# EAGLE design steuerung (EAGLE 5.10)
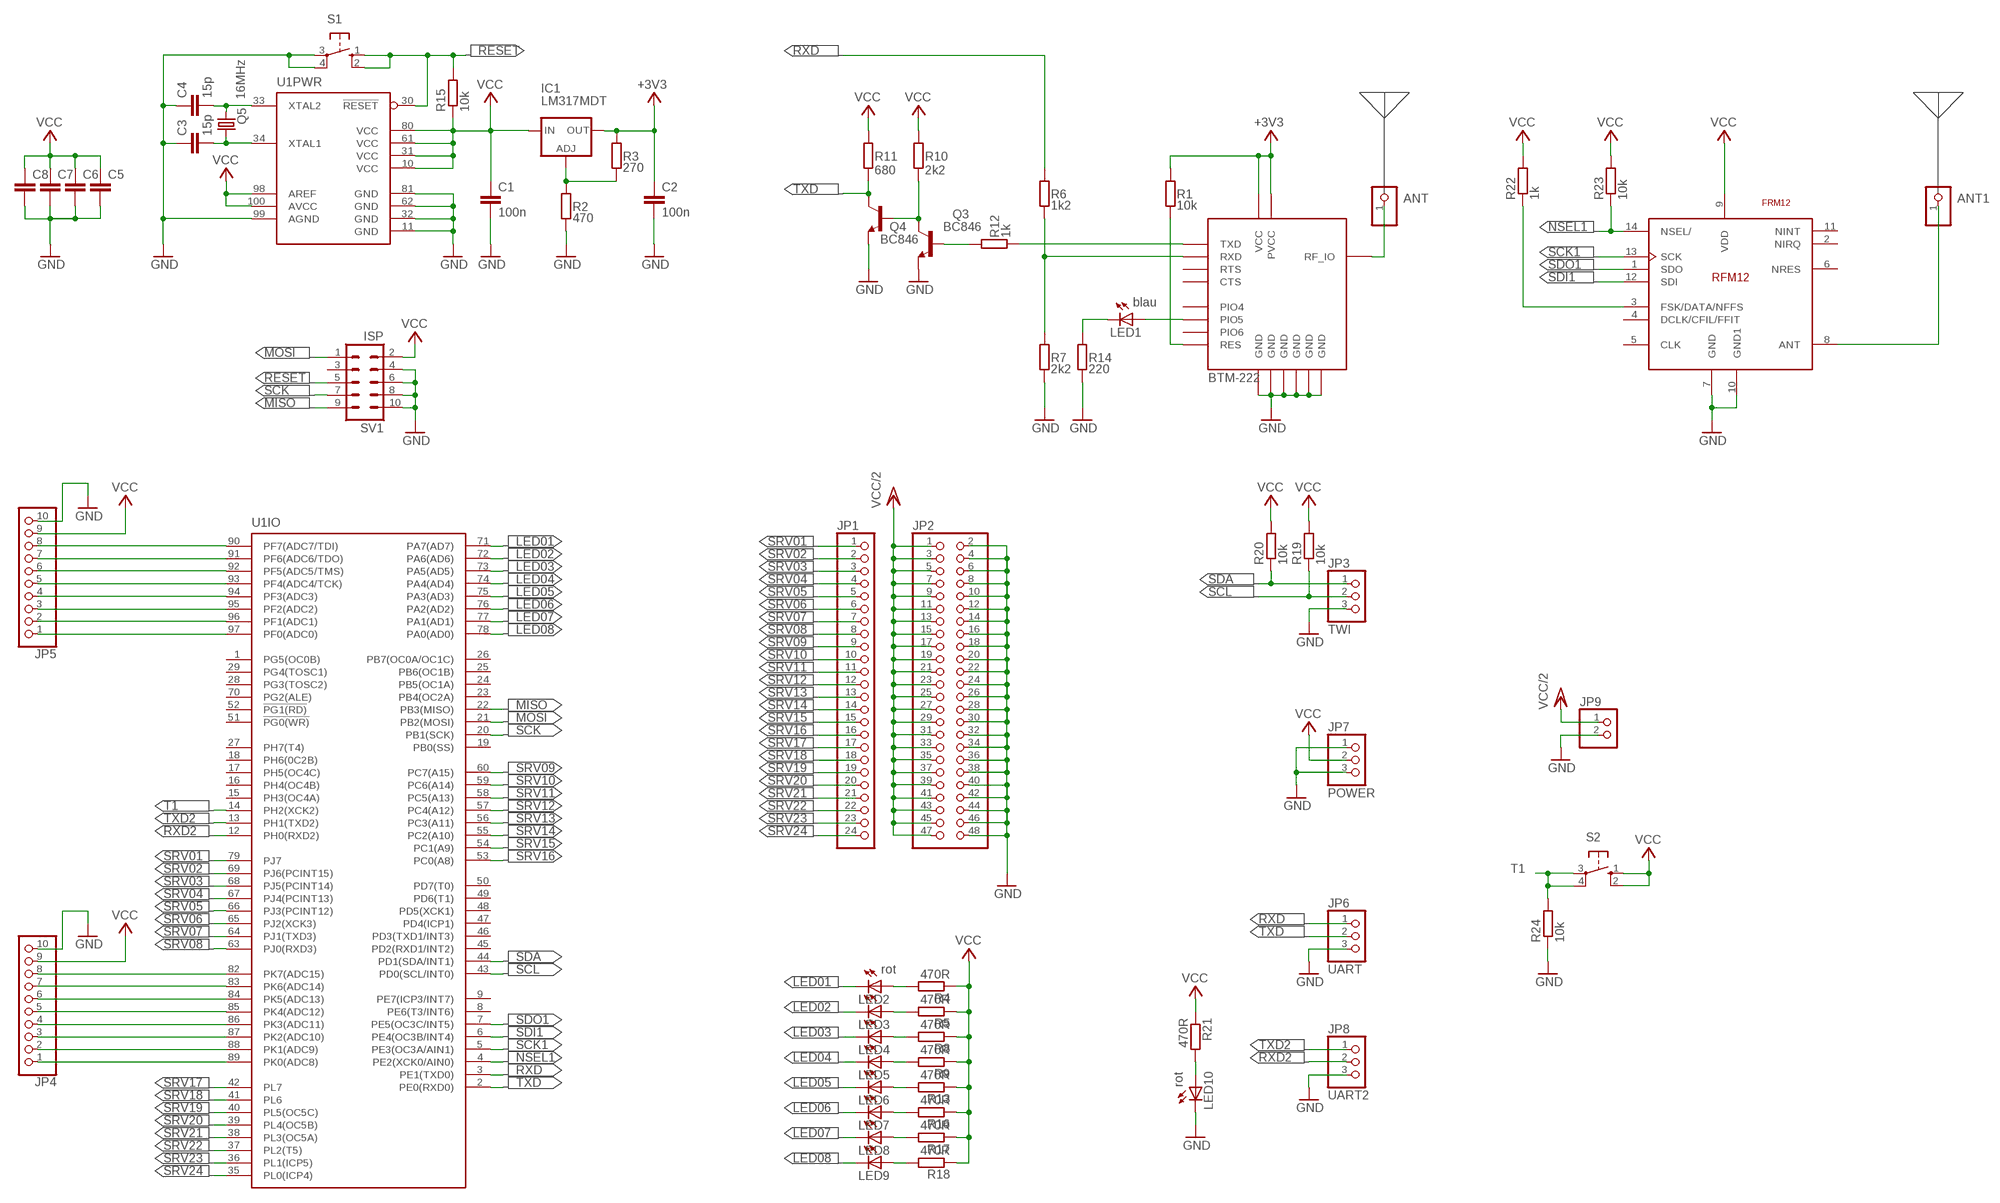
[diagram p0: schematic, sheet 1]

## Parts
ANT  PINHD-1X1  [1X01]
ANT1  PINHD-1X1  [1X01]
C1  100n  C-EUC0805  [C0805]
C2  100n  C-EUC0805  [C0805]
C3  15p  C-EUC0805  [C0805]
C4  15p  C-EUC0805  [C0805]
C5  C-EUC0805  [C0805]
C6  C-EUC0805  [C0805]
C7  C-EUC0805  [C0805]
C8  C-EUC0805  [C0805]
IC1  LM317MDT  [DPACK]
IC4  BTM_SER  [BTM_222]
JP1  PINHD-1X24  [1X24]
JP2  PINHD-2X24  [2X24]
JP3  TWI  PINHD-1X3  [1X03]
JP4  PINHD-1X10  [1X10]
JP5  PINHD-1X10  [1X10]
JP6  UART  PINHD-1X3  [1X03]
JP7  POWER  PINHD-1X3  [1X03]
JP8  UART2  PINHD-1X3  [1X03]
JP9  PINHD-1X2  [1X02]
LED1  LEDCHIP-LED0805  [CHIP-LED0805]
LED2  LEDCHIP-LED0805  [CHIP-LED0805]
LED3  LEDCHIP-LED0805  [CHIP-LED0805]
LED4  LEDCHIP-LED0805  [CHIP-LED0805]
LED5  LEDCHIP-LED0805  [CHIP-LED0805]
LED6  LEDCHIP-LED0805  [CHIP-LED0805]
LED7  LEDCHIP-LED0805  [CHIP-LED0805]
LED8  LEDCHIP-LED0805  [CHIP-LED0805]
LED9  LEDCHIP-LED0805  [CHIP-LED0805]
LED10  LEDCHIP-LED0805  [CHIP-LED0805]
Q3  BC846  BC846ALT1SMD  [SOT23]
Q4  BC846  BC846ALT1SMD  [SOT23]
Q5  16MHz  CRYSTALHC49U-V  [HC49U-V]
R1  10k  R-EU_M0805  [M0805]
R2  470  R-EU_M0805  [M0805]
R3  270  R-EU_M0805  [M0805]
R4  470R  R-EU_M0805  [M0805]
R5  470R  R-EU_M0805  [M0805]
R6  1k2  R-EU_M0805  [M0805]
R7  2k2  R-EU_M0805  [M0805]
R8  470R  R-EU_M0805  [M0805]
R9  470R  R-EU_M0805  [M0805]
R10  2k2  R-EU_M0805  [M0805]
R11  680  R-EU_M0805  [M0805]
R12  1k  R-EU_M0805  [M0805]
R13  470R  R-EU_M0805  [M0805]
R14  220  R-EU_M0805  [M0805]
R15  10k  R-EU_M0805  [M0805]
R16  470R  R-EU_M0805  [M0805]
R17  470R  R-EU_M0805  [M0805]
R18  470R  R-EU_M0805  [M0805]
R19  10k  R-EU_M0805  [M0805]
R20  10k  R-EU_M0805  [M0805]
R21  470R  R-EU_M0805  [M0805]
R22  1k  R-EU_M0805  [M0805]
R23  10k  R-EU_M0805  [M0805]
R24  10k  R-EU_M0805  [M0805]
S1  10-XX  [B3F-10XX]
S2  10-XX  [B3F-10XX]
SV1  ISP  ML10  [ML10]
U1  ATMEGA640  [TQFP100]
U$1  FRM12  [RFM12]

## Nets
+3V3: C2.1 IC1.4(OUT) IC4.P$2(PVCC) IC4.P$17(VCC) R1.2 R3.2
GND: C1.2 C2.2 C3.1 C4.1 C5.2 C6.2 C7.2 C8.2 IC4.P$1(GND) IC4.P$10(GND) IC4.P$18(GND) IC4.P$19(GND) IC4.P$29(GND) IC4.P$38(GND) JP2.2 JP2.4 JP2.6 JP2.8 JP2.10 JP2.12 JP2.14 JP2.16 JP2.18 JP2.20 JP2.22 JP2.24 JP2.26 JP2.28 JP2.30 JP2.32 JP2.34 JP2.36 JP2.38 JP2.40 JP2.42 JP2.44 JP2.46 JP2.48 JP3.3 JP4.10 JP5.10 JP6.3 JP7.1 JP7.3 JP8.3 JP9.2 LED10.C Q3.2(E) Q4.2(E) R2.1 R7.1 R14.1 R24.1 S1.3(P) S1.4(P1) SV1.4 SV1.6 SV1.8 SV1.10 U1.11(PWR:GND) U1.32(PWR:GND) U1.62(PWR:GND) U1.81(PWR:GND) U1.99(PWR:AGND) U$1.7(GND) U$1.10(GND1)
LED01: LED2.C U1.71(IO:PA7(AD7))
LED02: LED3.C U1.72(IO:PA6(AD6))
LED03: LED4.C U1.73(IO:PA5(AD5))
LED04: LED5.C U1.74(IO:PA4(AD4))
LED05: LED6.C U1.75(IO:PA3(AD3))
LED06: LED7.C U1.76(IO:PA2(AD2))
LED07: LED8.C U1.77(IO:PA1(AD1))
LED08: LED9.C U1.78(IO:PA0(AD0))
MISO: SV1.9 U1.22(IO:PB3(MISO))
MOSI: SV1.1 U1.21(IO:PB2(MOSI))
N$1: LED2.A R4.2
N$2: IC1.1(ADJ) R2.2 R3.1
N$3: IC4.P$27(TXD) R12.1
N$4: LED3.A R5.2
N$5: IC4.P$26(RXD) R6.1 R7.2
N$6: ANT.1 IC4.P$37(RF_IO)
N$7: C3.2 Q5.1 U1.34(PWR:XTAL1)
N$8: LED4.A R8.2
N$9: Q3.3(C) Q4.1(B) R10.2
N$10: IC4.P$11(PIO5) LED1.A
N$11: LED5.A R9.2
N$12: Q3.1(B) R12.2
N$13: LED1.C R14.2
N$14: LED6.A R13.2
N$15: C4.2 Q5.2 U1.33(PWR:XTAL2)
N$16: LED7.A R16.2
N$17: LED8.A R17.2
N$18: LED9.A R18.2
N$19: JP5.1 U1.97(IO:PF0(ADC0))
N$20: JP5.2 U1.96(IO:PF1(ADC1))
N$21: JP5.3 U1.95(IO:PF2(ADC2))
N$22: JP5.4 U1.94(IO:PF3(ADC3))
N$23: IC4.P$16(RES) R1.1
N$24: JP5.5 U1.93(IO:PF4(ADC4/TCK))
N$25: JP5.6 U1.92(IO:PF5(ADC5/TMS))
N$26: JP5.7 U1.91(IO:PF6(ADC6/TDO))
N$27: JP5.8 U1.90(IO:PF7(ADC7/TDI))
N$28: JP4.1 U1.89(IO:PK0(ADC8))
N$29: JP4.2 U1.88(IO:PK1(ADC9))
N$30: JP4.3 U1.87(IO:PK2(ADC10))
N$31: JP4.4 U1.86(IO:PK3(ADC11))
N$32: JP4.5 U1.85(IO:PK4(ADC12))
N$33: JP4.6 U1.84(IO:PK5(ADC13))
N$34: JP4.7 U1.83(IO:PK6(ADC14))
N$35: JP4.8 U1.82(IO:PK7(ADC15))
N$36: LED10.A R21.2
N$39: ANT1.1 U$1.8(ANT)
N$41: R22.1 U$1.3(FSK/DATA/NFFS)
NSEL1: R23.1 U1.4(IO:PE2(XCK0/AIN0)) U$1.14(NSEL/)
RESET: R15.2 S1.1(S) S1.2(S1) SV1.5 U1.30(PWR:!RESET)
RXD: JP6.1 R6.2 U1.3(IO:PE1(TXD0))
RXD2: JP8.2 U1.12(IO:PH0(RXD2))
SCK: SV1.7 U1.20(IO:PB1(SCK))
SCK1: U1.5(IO:PE3(OC3A/AIN1)) U$1.13(SCK)
SCL: JP3.2 R19.1 U1.43(IO:PD0(SCL/INT0))
SDA: JP3.1 R20.1 U1.44(IO:PD1(SDA/INT1))
SDI1: U1.6(IO:PE4(OC3B/INT4)) U$1.12(SDI)
SDO1: U1.7(IO:PE5(OC3C/INT5)) U$1.1(SDO)
SRV01: JP1.1 U1.79(IO:PJ7)
SRV02: JP1.2 U1.69(IO:PJ6(PCINT15))
SRV03: JP1.3 U1.68(IO:PJ5(PCINT14))
SRV04: JP1.4 U1.67(IO:PJ4(PCINT13))
SRV05: JP1.5 U1.66(IO:PJ3(PCINT12))
SRV06: JP1.6 U1.65(IO:PJ2(XCK3))
SRV07: JP1.7 U1.64(IO:PJ1(TXD3))
SRV08: JP1.8 U1.63(IO:PJ0(RXD3))
SRV09: JP1.9 U1.60(IO:PC7(A15))
SRV10: JP1.10 U1.59(IO:PC6(A14))
SRV11: JP1.11 U1.58(IO:PC5(A13))
SRV12: JP1.12 U1.57(IO:PC4(A12))
SRV13: JP1.13 U1.56(IO:PC3(A11))
SRV14: JP1.14 U1.55(IO:PC2(A10))
SRV15: JP1.15 U1.54(IO:PC1(A9))
SRV16: JP1.16 U1.53(IO:PC0(A8))
SRV17: JP1.17 U1.42(IO:PL7)
SRV18: JP1.18 U1.41(IO:PL6)
SRV19: JP1.19 U1.40(IO:PL5(OC5C))
SRV20: JP1.20 U1.39(IO:PL4(OC5B))
SRV21: JP1.21 U1.38(IO:PL3(OC5A))
SRV22: JP1.22 U1.37(IO:PL2(T5))
SRV23: JP1.23 U1.36(IO:PL1(ICP5))
SRV24: JP1.24 U1.35(IO:PL0(ICP4))
T1: R24.2 S2.3(P) S2.4(P1) U1.14(IO:PH2(XCK2))
TXD: JP6.2 Q4.3(C) R11.2 U1.2(IO:PE0(RXD0))
TXD2: JP8.1 U1.13(IO:PH1(TXD2))
VCC: C1.1 C5.1 C6.1 C7.1 C8.1 IC1.3(IN) JP4.9 JP5.9 JP7.2 R4.1 R5.1 R8.1 R9.1 R10.1 R11.1 R13.1 R15.1 R16.1 R17.1 R18.1 R19.2 R20.2 R21.1 R22.2 R23.2 S2.1(S) S2.2(S1) SV1.2 U1.10(PWR:VCC) U1.31(PWR:VCC) U1.61(PWR:VCC) U1.80(PWR:VCC) U1.98(PWR:AREF) U1.100(PWR:AVCC) U$1.9(VDD)
VCC/2: JP2.1 JP2.3 JP2.5 JP2.7 JP2.9 JP2.11 JP2.13 JP2.15 JP2.17 JP2.19 JP2.21 JP2.23 JP2.25 JP2.27 JP2.29 JP2.31 JP2.33 JP2.35 JP2.37 JP2.39 JP2.41 JP2.43 JP2.45 JP2.47 JP9.1
Unconnected: IC4.P$9(PIO4) IC4.P$12(PIO6) IC4.P$28(RTS) IC4.P$30(CTS) SV1.3 U1.1(IO:PG5(OC0B)) U1.8(IO:PE6(T3/INT6)) U1.9(IO:PE7(ICP3/INT7)) U1.15(IO:PH3(OC4A)) U1.16(IO:PH4(OC4B)) U1.17(IO:PH5(OC4C)) U1.18(IO:PH6(0C2B)) U1.19(IO:PB0(SS)) U1.23(IO:PB4(OC2A)) U1.24(IO:PB5(OC1A)) U1.25(IO:PB6(OC1B)) U1.26(IO:PB7(OC0A/OC1C)) U1.27(IO:PH7(T4)) U1.28(IO:PG3(TOSC2)) U1.29(IO:PG4(TOSC1)) U1.45(IO:PD2(RXD1/INT2)) U1.46(IO:PD3(TXD1/INT3)) U1.47(IO:PD4(ICP1)) U1.48(IO:PD5(XCK1)) U1.49(IO:PD6(T1)) U1.50(IO:PD7(T0)) U1.51(IO:!PG0(WR)) U1.52(IO:!PG1(RD)) U1.70(IO:PG2(ALE)) U$1.2(NIRQ) U$1.4(DCLK/CFIL/FFIT) U$1.5(CLK) U$1.6(NRES) U$1.11(NINT)

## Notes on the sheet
- 680 | 2k2
- blau
- BTM-222
- rot
- rot

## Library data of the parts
ANT ANT1 = pinhead:PINHD-1X1: PIN HEADER
C1 C2 = rcl:C-EU: CAPACITOR, European symbol
C3-C8 = resistor:C-EU: CAPACITOR, European symbol
IC1 = v-reg:LM317?*: 500 mA Adjustable Output Positive Voltage Regulator Source: http://www.onsemi.co.jp .. LM317M-D.PDF
IC4 = BTM222:BTM_SER
JP1 = pinhead:PINHD-1X24: PIN HEADER
JP2 = pinhead:PINHD-2X24: PIN HEADER
JP3 JP6-JP8 = pinhead:PINHD-1X3: PIN HEADER
JP4 JP5 = pinhead:PINHD-1X10: PIN HEADER
JP9 = pinhead:PINHD-1X2: PIN HEADER
LED1-LED10 = led:LED: LED
Q3 Q4 = transistor-npn:BC846*: NPN Transistor
Q5 = crystal:CRYSTAL: CRYSTAL
R1-R3 R6 R7 R10-R12 R14 = rcl:R-EU_: RESISTOR, European symbol
R4 R5 R8 R9 R13 R15-R24 = resistor:R-EU_: RESISTOR, European symbol
S1 S2 = switch-omron:10-XX: OMRON SWITCH
SV1 = con-harting-ml:ML10: HARTING
U1 = ATmega640:ATMEGA640
U$1 = RFM12:FRM12

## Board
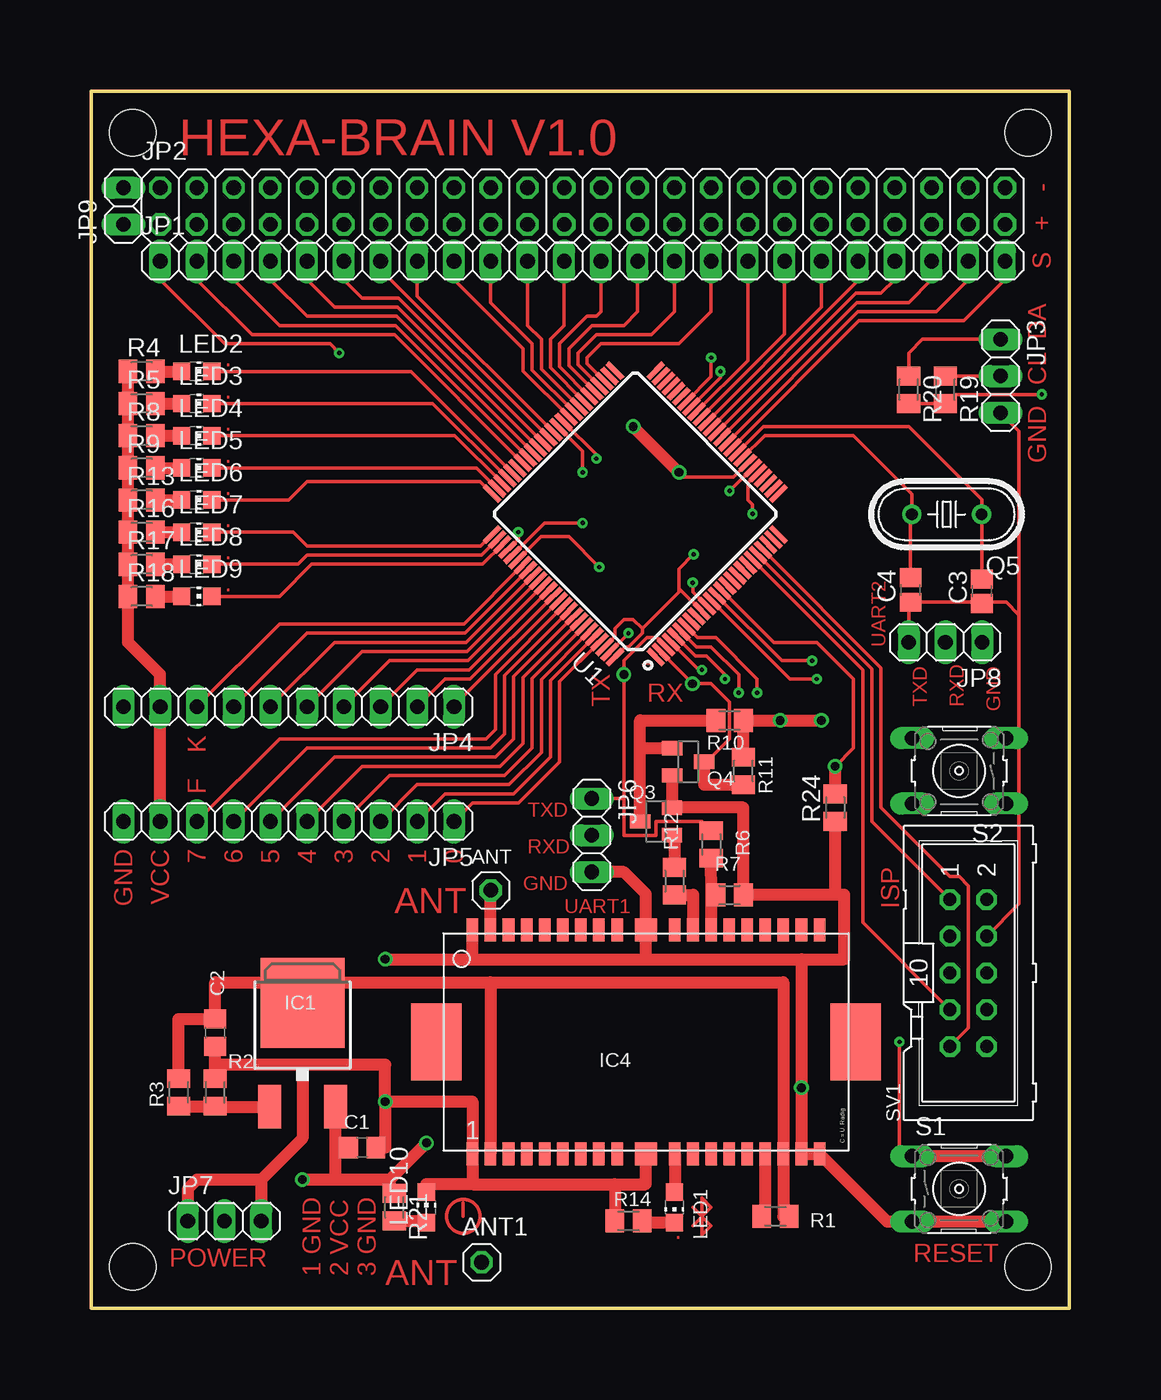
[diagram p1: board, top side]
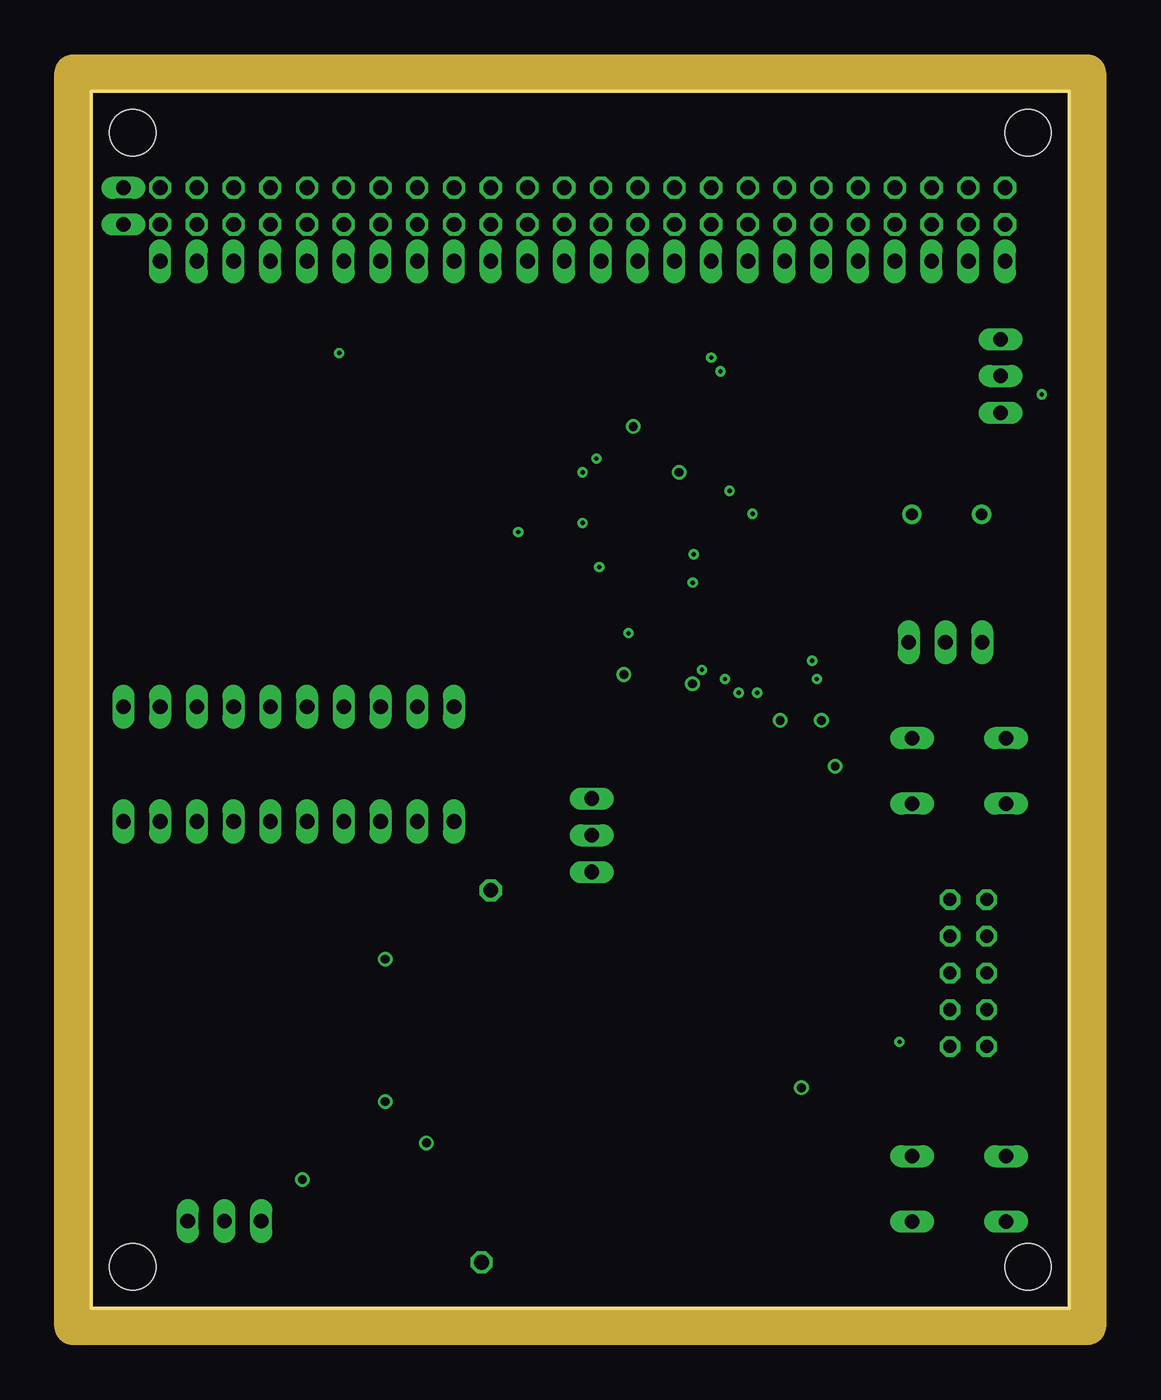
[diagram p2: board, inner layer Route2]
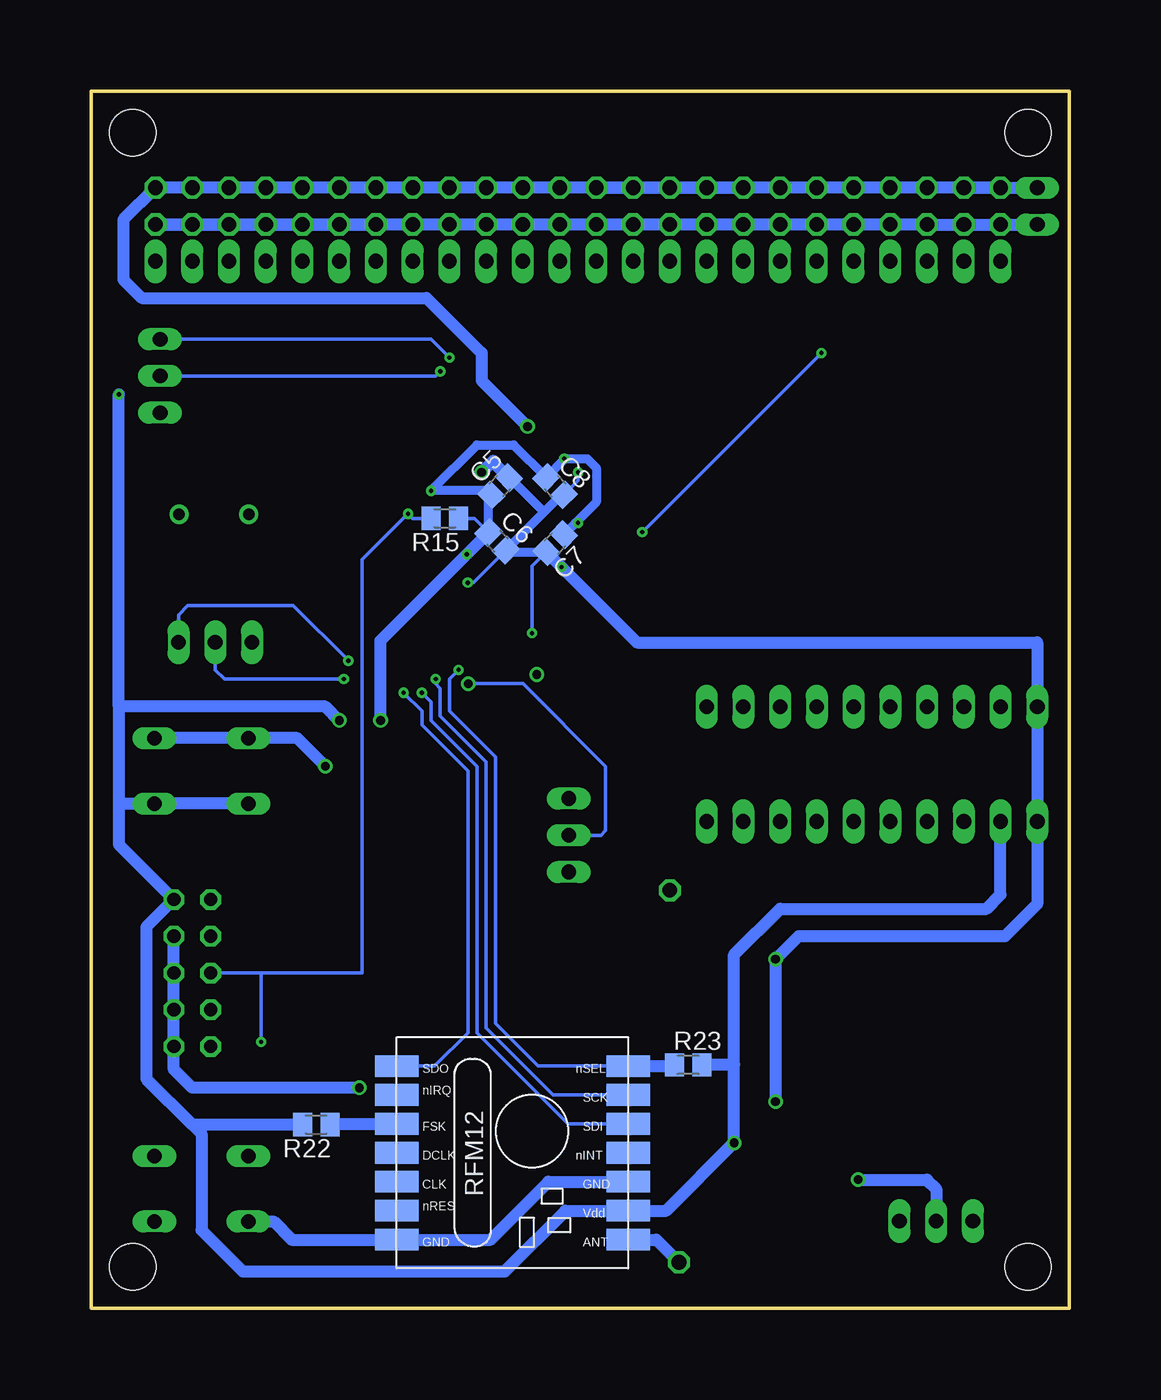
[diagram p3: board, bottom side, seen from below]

Size 67.63 x 84.14 mm. Coordinates in mm from the lower left corner, seen from the top.
Outline: 0,0 67.63,0 67.63,84.14 0,84.14 0,0
Copper layers (1*16): Top 0.035mm / dielectric 1.5mm / Bottom 0.035mm
Design rules "default *": minimum track width 10mil, minimum drill 24mil, track to track 8mil, track to pad 8mil, pad to pad 8mil, via to via 8mil, smd to smd 8mil, copper to edge 40mil, drill to drill 8mil, minimum pad ring 10mil, minimum via ring 8mil, stop-mask expansion 0mil, vias tented up to drill 0mil, thermal gap 10mil
Holes 3.2 mm at 2.86,81.28 64.77,81.28 2.86,2.86 64.77,2.86

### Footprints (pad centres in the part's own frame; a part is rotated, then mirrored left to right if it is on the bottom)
1X01 = drill 1.016 octagon: 1 0,0
C0805 = smd 1.3 x 1.5: 1 -0.95,0; 2 0.95,0
C0805' = smd 1.3 x 1.5: 1 -0.85,0; 2 0.85,0
DPACK = smd 1.6 x 3: 1 -2.28,-4.8; 3 2.28,-4.8 | smd 5.8 x 6.2: 4 0,2.38
BTM_222 = smd 0.8 x 1.6: P$1 -11.43,-7.75; P$2 -10.18,-7.75; P$3 -8.93,-7.75; P$4 -7.68,-7.75; P$5 -6.43,-7.75; P$6 -5.18,-7.75; P$7 -3.93,-7.75; P$8 -2.68,-7.75; P$9 -1.43,-7.75; P$11 2.57,-7.75; P$12 3.82,-7.75; P$13 5.07,-7.75; P$14 6.32,-7.75; P$15 7.57,-7.75; P$16 8.82,-7.75; P$17 10.07,-7.75; P$18 11.32,-7.75; P$19 12.57,-7.75; P$20 12.57,7.75; P$21 11.32,7.75; P$22 10.07,7.75; P$23 8.82,7.75; P$24 7.57,7.75; P$25 6.32,7.75; P$26 5.07,7.75; P$27 3.82,7.75; P$28 2.57,7.75; P$30 -1.43,7.75; P$31 -2.68,7.75; P$32 -3.93,7.75; P$33 -5.18,7.75; P$34 -6.43,7.75; P$35 -7.68,7.75; P$36 -8.93,7.75; P$37 -10.18,7.75; P$38 -11.43,7.75 | smd 1.5 x 1.6: P$10 0.57,-7.75; P$29 0.57,7.75 | smd 3.5 x 5.3: P$39 -13.93,0; P$40 15.07,0
1X24 = drill 1.016 long: 1 -29.21,0; 2 -26.67,0; 3 -24.13,0; 4 -21.59,0; 5 -19.05,0; 6 -16.51,0; 7 -13.97,0; 8 -11.43,0; 9 -8.89,0; 10 -6.35,0; 11 -3.81,0; 12 -1.27,0; 13 1.27,0; 14 3.81,0; 15 6.35,0; 16 8.89,0; 17 11.43,0; 18 13.97,0; 19 16.51,0; 20 19.05,0; 21 21.59,0; 22 24.13,0; 23 26.67,0; 24 29.21,0
2X24 = drill 1.016 octagon: 1 -27.94,-1.27; 2 -27.94,1.27; 3 -25.4,-1.27; 4 -25.4,1.27; 5 -22.86,-1.27; 6 -22.86,1.27; 7 -20.32,-1.27; 8 -20.32,1.27; 9 -17.78,-1.27; 10 -17.78,1.27; 11 -15.24,-1.27; 12 -15.24,1.27; 13 -12.7,-1.27; 14 -12.7,1.27; 15 -10.16,-1.27; 16 -10.16,1.27; 17 -7.62,-1.27; 18 -7.62,1.27; 19 -5.08,-1.27; 20 -5.08,1.27; 21 -2.54,-1.27; 22 -2.54,1.27; 23 0,-1.27; 24 0,1.27; 25 2.54,-1.27; 26 2.54,1.27; 27 5.08,-1.27; 28 5.08,1.27; 29 7.62,-1.27; 30 7.62,1.27; 31 10.16,-1.27; 32 10.16,1.27; 33 12.7,-1.27; 34 12.7,1.27; 35 15.24,-1.27; 36 15.24,1.27; 37 17.78,-1.27; 38 17.78,1.27; 39 20.32,-1.27; 40 20.32,1.27; 41 22.86,-1.27; 42 22.86,1.27; 43 25.4,-1.27; 44 25.4,1.27; 45 27.94,-1.27; 46 27.94,1.27; 47 30.48,-1.27; 48 30.48,1.27
1X03 = drill 1.016 long: 1 -2.54,0; 2 0,0; 3 2.54,0
1X10 = drill 1.016 long: 1 -11.43,0; 2 -8.89,0; 3 -6.35,0; 4 -3.81,0; 5 -1.27,0; 6 1.27,0; 7 3.81,0; 8 6.35,0; 9 8.89,0; 10 11.43,0
1X02 = drill 1.016 long: 1 -1.27,0; 2 1.27,0
CHIP-LED0805 = smd 1.2 x 1.2: A 0,-1.05; C 0,1.05
SOT23 = smd 1 x 1.4: 1 -0.95,-1.1; 2 0.95,-1.1; 3 0,1.1
HC49U-V = drill 0.813 round: 1 -2.413,0; 2 2.413,0
M0805 = smd 1.3 x 1.6: 1 -0.95,0; 2 0.95,0
B3F-10XX = drill 1.016 long: 1 -3.251,2.261; 2 3.251,2.261; 3 -3.251,-2.261; 4 3.251,-2.261
ML10 = drill 0.914 octagon: 1 -5.08,-1.27; 2 -5.08,1.27; 3 -2.54,-1.27; 4 -2.54,1.27; 5 0,-1.27; 6 0,1.27; 7 2.54,-1.27; 8 2.54,1.27; 9 5.08,-1.27; 10 5.08,1.27
TQFP100 = smd 1.5 x 0.35: 1 -8,6; 2 -8,5.5; 3 -8,5; 4 -8,4.5; 5 -8,4; 6 -8,3.5; 7 -8,3; 8 -8,2.5; 9 -8,2; 10 -8,1.5; 11 -8,1; 12 -8,0.5; 13 -8,0; 14 -8,-0.5; 15 -8,-1; 16 -8,-1.5; 17 -8,-2; 18 -8,-2.5; 19 -8,-3; 20 -8,-3.5; 21 -8,-4; 22 -8,-4.5; 23 -8,-5; 24 -8,-5.5; 25 -8,-6; 51 8,-6; 52 8,-5.5; 53 8,-5; 54 8,-4.5; 55 8,-4; 56 8,-3.5; 57 8,-3; 58 8,-2.5; 59 8,-2; 60 8,-1.5; 61 8,-1; 62 8,-0.5; 63 8,0; 64 8,0.5; 65 8,1; 66 8,1.5; 67 8,2; 68 8,2.5; 69 8,3; 70 8,3.5; 71 8,4; 72 8,4.5; 73 8,5; 74 8,5.5; 75 8,6 | smd 0.35 x 1.5: 26 -6,-8; 27 -5.5,-8; 28 -5,-8; 29 -4.5,-8; 30 -4,-8; 31 -3.5,-8; 32 -3,-8; 33 -2.5,-8; 34 -2,-8; 35 -1.5,-8; 36 -1,-8; 37 -0.5,-8; 38 0,-8; 39 0.5,-8; 40 1,-8; 41 1.5,-8; 42 2,-8; 43 2.5,-8; 44 3,-8; 45 3.5,-8; 46 4,-8; 47 4.5,-8; 48 5,-8; 49 5.5,-8; 50 6,-8; 76 6,8; 77 5.5,8; 78 5,8; 79 4.5,8; 80 4,8; 81 3.5,8; 82 3,8; 83 2.5,8; 84 2,8; 85 1.5,8; 86 1,8; 87 0.5,8; 88 0,8; 89 -0.5,8; 90 -1,8; 91 -1.5,8; 92 -2,8; 93 -2.5,8; 94 -3,8; 95 -3.5,8; 96 -4,8; 97 -4.5,8; 98 -5,8; 99 -5.5,8; 100 -6,8
RFM12 = smd 1.5 x 3: 1 -5,-10; 2 -3,-10; 3 -1,-10; 4 1,-10; 5 3,-10; 6 5,-10; 7 7,-10; 8 7,6; 9 5,6; 10 3,6; 11 1,6; 12 -1,6; 13 -3,6; 14 -5,6

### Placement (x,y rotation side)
ANT  27.62,28.89 0 top
ANT1  26.99,3.17 0 top
C1  18.73,11.11 0 top
C2  8.57,19.05 270 top
C3  15p  [C0805']  61.58,49.57 90 top
C4  15p  [C0805']  56.65,49.66 90 top
C5  [C0805']  39.37,56.83 45 bottom
C6  [C0805']  39.56,53.02 315 bottom
C7  [C0805']  35.56,52.89 225 bottom
C8  [C0805']  35.56,56.83 315 bottom
IC1  14.61,18.73 0 top
IC4  37.78,18.42 0 top
JP1  33.97,72.39 0 top
JP2  32.7,76.2 0 top
JP3  62.87,64.45 270 top
JP4  13.65,41.59 180 top
JP5  13.65,33.66 180 top
JP6  34.61,32.7 270 top
JP7  9.21,6.03 0 top
JP8  59.05,46.04 180 top
JP9  2.22,76.2 90 top
LED1  40.32,6.98 180 top
LED2  7.3,64.77 270 top
LED3  7.3,62.55 270 top
LED4  7.3,60.33 270 top
LED5  7.3,58.1 270 top
LED6  7.3,55.88 270 top
LED7  7.3,53.66 270 top
LED8  7.3,51.44 270 top
LED9  7.3,49.21 270 top
LED10  23.18,6.98 0 top
Q3  39.05,33.66 90 top
Q4  41.27,37.78 270 top
Q5  59.15,54.89 180 top
R1  47.31,6.35 0 top
R2  8.57,14.92 270 top
R3  6.03,14.92 90 top
R4  3.49,64.77 0 top
R5  3.49,62.55 0 top
R6  42.86,32.07 90 top
R7  44.13,28.58 180 top
R8  3.49,60.33 0 top
R9  3.49,58.1 0 top
R10  44.13,40.64 180 top
R11  45.09,37.15 270 top
R12  40.32,29.53 90 top
R13  3.49,55.88 0 top
R14  37.15,6.03 0 top
R15  43.18,54.61 180 bottom
R16  3.49,53.66 0 top
R17  3.49,51.44 0 top
R18  3.49,49.21 0 top
R19  59.05,63.5 270 top
R20  56.52,63.5 270 top
R21  20.95,6.98 270 top
R22  52.07,12.7 180 bottom
R23  26.35,16.83 0 bottom
R24  51.44,34.61 90 top
S1  60.01,8.26 0 top
S2  60.01,37.15 180 top
SV1  60.64,23.18 270 top
U1  37.61,54.91 135 top
U$1  36.51,11.75 270 bottom

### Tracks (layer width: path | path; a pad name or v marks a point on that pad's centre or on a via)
+3V3
  Top 0.813: 14.61,22.54 IC1.4 | 14.61,22.54 27.6,22.54 | 27.6,22.54 IC4.P$2 | 27.6,22.54 47.85,22.54 IC4.P$17 47.85,6.35 R1.2 | 14.61,22.54 8.57,22.54 C2.1 6.03,20 R3.2
GND  (via drill 0.3, 0.3 pad 0.61, 0.6)
  Top 0.254: U1.81 31.09,53.34 33.02,53.34 v35.12,51.24 | v33.97,57.79 33.97,59.26 U1.62 | U1.32 44.41,57.47 40.96,57.47 v40.64,57.79 | v41.59,50.17 41.59,49.52 U1.11 | U1.99 36.83,46.35 v37.15,46.67 | C3.1 61.49,48.81 C4.1 | C4.1 63.27,48.81 64.14,47.94 | 64.14,47.94 64.14,27.94 SV1.4 | JP3.3 64.14,60.64 64.14,47.94 | JP8.3 56.52,48.68 C4.1
  Top 0.813: 26.35,24.13 IC4.P$38 | 26.35,24.13 38.35,24.13 | 38.35,24.13 IC4.P$29 38.35,28.64 36.83,30.16 JP6.3 | 38.35,24.13 49.1,24.13 | 26.35,8.57 IC4.P$1 26.35,14.29 v20.32,14.29 | 36.2,8.57 38.35,8.57 IC4.P$10 | v20.32,24.13 26.35,24.13 | 36.2,8.57 R14.1 | 26.35,8.57 36.2,8.57 | C2.2 R2.1 8.57,16.83 14.61,16.83 | 14.61,16.83 20.32,16.83 v20.32,14.29 | C1.2 20.32,11.11 v20.32,14.29 | 51.44,28.58 52.07,28.58 52.07,24.13 49.1,24.13 | 51.44,28.58 R7.1 45.08,34.61 40.17,34.61 | 40.17,34.61 Q3.2 | 40.17,34.61 Q4.2 | 49.1,24.13 v49.1,15.24 IC4.P$18 IC4.P$19 55.02,5.99 S1.3 S1.4 | 14.61,16.83 14.61,11.75 11.75,8.89 | 11.75,8.89 JP7.3 | JP7.1 6.67,8.26 7.3,8.89 11.75,8.89 | LED10.C 23.18,8.57 26.35,8.57 | v37.47,60.96 v40.64,57.79 | 51.44,28.58 R24.1
  Bottom 0.254: C8.2 33.97,57.22 v33.97,57.79 | 38.95,52.17 C6.2 41.21,50.17 v41.59,50.17 | v37.15,46.67 37.15,51.3 C7.2
  Bottom 0.61: C7.2 38.82,52.29 C6.2 36.32,55.05 | C8.2 35.15,56.23 36.32,55.05 | C5.2 38.7,57.43 36.32,55.05
  Bottom 0.813: v20.32,14.29 v20.32,24.13 18.73,25.72 4.45,25.72 2.22,27.94 JP5.10 JP4.10 2.22,46.04 29.91,46.04 v35.12,51.24 C7.2 | SV1.4 SV1.6 SV1.8 SV1.10 61.91,16.51 60.64,15.24 v49.1,15.24 | JP2.2 JP2.4 JP2.6 JP2.8 JP2.10 JP2.12 JP2.14 JP2.16 JP2.18 JP2.20 JP2.22 JP2.24 | JP2.24 JP2.26 JP2.28 JP2.30 JP2.32 JP2.34 JP2.36 JP2.38 JP2.40 JP2.42 JP2.44 JP2.46 JP2.48 65.41,75.25 65.41,71.12 64.14,69.85 44.45,69.85 40.64,66.04 40.64,64.13 v37.47,60.96 | JP2.2 JP2.24 | S1.3 55.02,5.99 53.78,4.75 U$1.7 40.02,4.75 36.02,8.75 U$1.10 | JP2.2 JP9.2 | C5.2 39.85,58.51 39.85,58.58 v40.64,57.79
LED01
  Top 0.254: U1.71 22.1,64.77 LED2.C
LED02
  Top 0.254: U1.72 23.61,62.55 LED3.C
LED03
  Top 0.254: U1.73 25.13,60.33 LED4.C
LED04
  Top 0.254: U1.74 26.64,58.1 LED5.C
LED05
  Top 0.254: U1.75 26.89,57.15 14.92,57.15 13.65,55.88 LED6.C
LED06
  Top 0.254: U1.76 26.92,52.7 14.92,52.7 13.97,53.66 LED7.C
LED07
  Top 0.254: U1.77 26.99,52.07 14.92,52.07 14.29,51.43 LED8.C
LED08
  Top 0.254: U1.78 27.07,51.43 15.24,51.43 13.02,49.21 LED9.C
MISO
  Top 0.254: SV1.9 60.64,19.37 60.64,29.21 60.01,29.85 59.37,29.85 54.61,34.61 54.61,44.28 U1.22
MOSI
  Top 0.254: U1.21 53.98,44.21 53.98,33.65 SV1.1
N$1
  Top 0.813: R4.2 LED2.A
N$2
  Top 0.813: IC1.1 8.57,13.93 R2.2 R3.1
N$3
  Top 0.813: R12.1 41.6,28.58 IC4.P$27
N$4
  Top 0.813: R5.2 LED3.A
N$5
  Top 0.813: IC4.P$26 42.87,26.17 42.86,28.57 | 42.86,28.57 R6.1 | R7.2 42.86,28.58 42.86,28.57
N$6
  Top 0.813: IC4.P$37 27.6,26.99 ANT.1
N$7
  Top 0.254: C3.2 61.58,54.87 Q5.1 61.56,55.91 56.52,60.96 46.49,60.96 U1.34
N$8
  Top 0.813: R8.2 LED4.A
N$9
  Top 0.813: Q3.3 37.95,38.73 | 37.95,38.73 Q4.1 | R10.2 37.95,40.64 37.95,38.73
N$10
  Top 0.813: IC4.P$11 40.35,8.03 LED1.A
N$11
  Top 0.813: R9.2 LED5.A
N$12
  Top 0.813: Q3.1 40.32,32.71 R12.2
N$13
  Top 0.813: R14.2 38.1,5.93 LED1.C
N$14
  Top 0.813: R13.2 LED6.A
N$15
  Top 0.254: C4.2 56.65,54.8 Q5.2 56.73,56.3 52.7,60.33 46.56,60.33 U1.33
N$16
  Top 0.813: R16.2 LED7.A
N$17
  Top 0.813: R17.2 LED8.A
N$18
  Top 0.813: R18.2 LED9.A
N$19
  Top 0.254: U1.97 32.38,43.32 32.38,37.78 29.53,34.93 26.35,34.93 JP5.1
N$20
  Top 0.254: JP5.2 24.45,35.56 29.21,35.56 31.75,38.1 31.75,43.39 U1.96
N$21
  Top 0.254: JP5.3 22.54,36.19 28.89,36.19 31.11,38.42 31.11,43.46 U1.95
N$22
  Top 0.254: JP5.4 20.64,36.83 28.57,36.83 30.48,38.73 30.48,43.54 U1.94
N$23
  Top 0.813: R1.1 46.6,6.35 IC4.P$16
N$24
  Top 0.254: JP5.5 18.73,37.47 28.26,37.47 29.84,39.05 29.84,43.61 U1.93
N$25
  Top 0.254: JP5.6 16.83,38.1 27.94,38.1 29.21,39.37 29.21,43.68 U1.92
N$26
  Top 0.254: JP5.7 14.92,38.73 27.62,38.73 28.57,39.69 28.57,43.75 U1.91
N$27
  Top 0.254: JP5.8 13.02,39.37 27.3,39.37 27.94,40 27.94,43.83 U1.90
N$28
  Top 0.254: JP4.1 25.08,41.67 U1.89
N$29
  Top 0.254: JP4.2 24.45,43.5 26.2,43.5 U1.88
N$30
  Top 0.254: JP4.3 22.54,44.13 26.13,44.13 U1.87
N$31
  Top 0.254: JP4.4 20.64,44.77 26.05,44.77 U1.86
N$32
  Top 0.254: JP4.5 18.73,45.4 25.98,45.4 U1.85
N$33
  Top 0.254: JP4.6 16.83,46.04 25.91,46.04 U1.84
N$34
  Top 0.254: JP4.7 14.92,46.67 25.84,46.67 U1.83
N$35
  Top 0.254: JP4.8 13.02,47.31 25.77,47.31 U1.82
N$36
  Top 0.813: R21.2 23.08,6.03 LED10.A
N$37
  Top 0.254: 25.72,7.3 25.72,6.35
N$38
  Top 0.254: 41.59,6.98 42.86,5.72 42.23,5.08 42.23,7.62 42.86,6.98 41.59,5.72
N$39
  Bottom 0.813: U$1.8 28.56,4.75 ANT1.1
N$40
  Route2 2.54: -1.27,85.41 68.9,85.41 68.9,-1.27 -1.27,-1.27 -1.27,85.41
N$41
  Bottom 0.813: U$1.3 46.56,12.7 R22.1
NSEL1  (via drill 0.3)
  Top 0.254: v42.23,44.13 42.03,44.13 U1.4
  Bottom 0.254: U$1.14 36.75,16.75 39.69,19.68 39.69,38.1 42.86,41.28 42.86,43.5 v42.23,44.13
  Bottom 0.813: U$1.14 27.38,16.75 R23.1
RESET  (via drill 0.3)
  Top 0.254: v45.72,54.93 45.72,55.56 45.4,55.88 45.4,57.04 U1.30 | v55.88,18.42 55.88,10.52 S1.1
  Top 0.813: S1.2 S1.1
  Bottom 0.254: R15.2 45.4,54.61 v45.72,54.93 48.9,51.75 48.9,23.18 55.88,23.18 | v55.88,18.42 55.88,23.18 | 55.88,23.18 SV1.5
RXD  (via drill 0.6)
  Top 0.254: R6.2 42.23,33.65 39.05,33.65 39.05,32.7 36.83,32.7 36.83,35.24 | 36.83,35.24 v36.83,43.82 36.83,44.77 38.42,46.36 39.1,46.36 U1.3 | JP6.1 36.83,35.24
RXD2  (via drill 0.3)
  Top 0.254: v50.16,43.5 48.32,43.5 U1.12
  Bottom 0.254: JP8.2 59.05,44.13 58.42,43.5 v50.16,43.5
SCK
  Top 0.254: U1.20 53.34,44.13 53.34,26.67 SV1.7
SCK1  (via drill 0.3)
  Top 0.254: U1.5 41.78,45.08 42.55,45.08 43.81,43.82 v43.81,43.5
  Bottom 0.254: U$1.13 35.7,14.75 40.32,19.37 40.32,37.78 43.5,40.96 43.5,42.86 43.81,43.18 v43.81,43.5
SCL  (via drill 0.3)
  Top 0.254: U1.43 43.5,64.33 v43.5,64.77 | R19.1 JP3.2
  Bottom 0.254: v43.5,64.77 43.81,64.45 JP3.2
SDA  (via drill 0.3)
  Top 0.254: U1.44 42.86,64.4 v42.86,65.72 | R20.1 56.52,66.04 57.47,66.99 JP3.1
  Bottom 0.254: v42.86,65.72 44.13,66.99 JP3.1
SDI1  (via drill 0.3)
  Top 0.254: U1.6 41.85,45.72 42.86,45.72 44.77,43.82 v44.77,42.54
  Bottom 0.254: v44.77,42.54 44.13,41.91 44.13,40.64 40.96,37.47 40.96,19.05 34.66,12.75 U$1.12
SDO1  (via drill 0.3)
  Top 0.254: U1.7 41.93,46.36 43.18,46.36 46.04,43.5 v46.04,42.54
  Bottom 0.254: U$1.1 43.9,16.75 41.59,19.05 41.59,37.15 44.77,40.32 44.77,41.28 v46.04,42.54
SRV01  (via drill 0.3)
  Top 0.254: JP1.1 4.76,71.12 9.21,66.68 16.51,66.68 v17.14,66.04 | U1.79 29.53,53.19 v29.53,53.66
  Bottom 0.254: v17.14,66.04 v29.53,53.66
SRV02
  Top 0.254: U1.69 20.97,67.31 11.11,67.31 7.3,71.12 JP1.2
SRV03
  Top 0.254: U1.68 21.04,67.95 13.02,67.95 9.84,71.12 JP1.3
SRV04
  Top 0.254: U1.67 21.12,68.58 14.92,68.58 12.38,71.12 JP1.4
SRV05
  Top 0.254: U1.66 21.19,69.22 16.83,69.22 14.92,71.12 JP1.5
SRV06
  Top 0.254: U1.65 21.26,69.85 18.73,69.85 17.46,71.12 JP1.6
SRV07
  Top 0.254: U1.64 20,71.81 JP1.7
SRV08
  Top 0.254: U1.63 22.54,69.98 JP1.8
SRV09
  Top 0.254: U1.60 29.84,64.8 29.84,66.36 25.08,71.12 JP1.9
SRV10
  Top 0.254: U1.59 30.48,64.87 30.48,66.68 27.62,69.53 JP1.10
SRV11
  Top 0.254: U1.58 31.11,64.94 31.11,66.99 30.16,67.95 JP1.11
SRV12
  Top 0.254: U1.57 31.75,65.02 31.75,66.99 32.7,67.95 JP1.12
SRV13
  Top 0.254: U1.56 32.38,65.09 32.38,66.68 34.29,68.58 34.92,68.58 35.24,68.9 JP1.13
SRV14
  Top 0.254: U1.55 33.02,65.16 33.02,66.36 34.61,67.95 36.83,67.95 37.78,68.9 JP1.14
SRV15
  Top 0.254: U1.54 33.66,65.23 33.66,66.04 34.92,67.31 38.73,67.31 40.32,68.9 JP1.15
SRV16
  Top 0.254: U1.53 34.29,65.3 34.29,65.72 35.24,66.68 40.64,66.68 42.86,68.9 JP1.16
SRV17
  Top 0.254: U1.42 45.4,65.53 JP1.17
SRV18
  Top 0.254: U1.41 47.94,67.36 JP1.18
SRV19
  Top 0.254: U1.40 50.48,69.2 JP1.19
SRV20
  Top 0.254: U1.39 53.02,71.03 JP1.20
SRV21
  Top 0.254: U1.38 52.87,70.17 54.61,70.17 55.56,71.12 JP1.21
SRV22
  Top 0.254: U1.37 52.94,69.53 56.52,69.53 58.1,71.12 JP1.22
SRV23
  Top 0.254: U1.36 53.01,68.9 58.42,68.9 60.64,71.12 JP1.23
SRV24
  Top 0.254: U1.35 53.09,68.26 60.33,68.26 63.18,71.12 JP1.24
T1  (via drill 0.6)
  Top 0.254: U1.14 47.19,46.04 50.16,46.04 52.7,43.5 52.7,38.73 v51.44,37.47
  Top 0.813: R24.2 v51.44,37.47
  Bottom 0.813: S2.3 S2.4 53.38,39.41 v51.44,37.47
TXD  (via drill 0.6)
  Top 0.254: U1.2 v41.57,43.18 42.86,43.18 44.13,41.91 44.13,39.37 42.55,37.78 Q4.3
  Top 0.813: Q4.3 42.38,36.2 R11.2
  Bottom 0.254: JP6.2 32.38,32.7 32.07,33.02 32.07,37.47 37.78,43.18 v41.57,43.18
TXD2  (via drill 0.3)
  Top 0.254: v49.85,44.77 47.76,44.77 U1.13
  Bottom 0.254: JP8.1 61.59,47.94 60.96,48.58 53.66,48.58 v49.85,44.77
VCC  (via drill 0.3, 0.3 pad 0.61, 0.6)
  Top 0.254: v33.97,54.29 31.34,54.29 U1.80 | v34.92,58.74 34.92,59.01 U1.61 | v44.13,56.52 44.17,56.52 U1.31 | 40.64,49.76 U1.10 | U1.98 36.2,46.42 36.2,46.99 36.83,47.62 37.47,47.62 38.1,46.99 | 38.1,46.99 38.1,46.67 37.15,45.72 36.91,45.72 U1.100 | 40.64,49.76 40.64,49.53 38.1,46.99 | 40.64,49.76 40.64,51.12 v41.65,52.13 | R20.2 R19.2 59.69,63.18 v65.72,63.18
  Top 0.813: 16.89,11.11 C1.1 | 16.89,11.11 IC1.3 | R11.1 R10.1 v47.62,40.64 v50.48,40.64 | 16.89,8.89 16.89,11.11 | 20.64,8.89 16.89,8.89 | v23.18,11.43 20.64,8.89 | R4.1 R5.1 R8.1 R9.1 R13.1 R16.1 R17.1 R18.1 2.54,46.04 4.76,43.82 JP4.9 JP5.9 | 16.89,8.89 v14.61,8.89 | R21.1 20.64,7.93 20.64,8.89
  Bottom 0.254: C7.1 34.77,53.49 | C8.1 36.16,57.5 | R15.1 41.14,54.61 C6.1
  Bottom 0.61: C6.1 40.16,56.05 C5.1 40.26,56.52 v44.13,56.52 40.96,59.69 38.42,59.69 C8.1 34.92,58.67 v34.92,58.74 33.34,58.74 32.7,58.1 32.7,55.75 34.16,54.29 | 34.16,54.29 v33.97,54.29 | 34.16,54.29 C7.1
  Bottom 0.813: C6.1 v41.65,52.13 47.62,46.16 v47.62,40.64 | v50.48,40.64 51.44,41.59 65.72,41.59 | 65.72,41.59 v65.72,63.18 | 65.72,41.59 65.72,34.89 | v14.61,8.89 9.84,8.89 9.21,8.26 JP7.2 | 23.18,16.83 23.18,24.45 20,27.62 5.71,27.62 4.76,28.58 JP5.9 | 23.18,16.83 v23.18,11.43 27.86,6.75 U$1.9 34.84,6.75 39.05,2.54 57.15,2.54 60.01,5.4 60.01,12.06 60.64,12.7 | 60.64,12.7 R22.2 | 60.64,12.7 63.82,15.87 63.82,26.35 SV1.2 65.72,32.07 65.72,34.89 | 23.18,16.83 R23.2 | 65.72,34.89 S2.1 S2.2
VCC/2
  Bottom 0.813: JP2.23 JP2.21 JP2.19 JP2.17 JP2.15 JP2.13 JP2.11 JP2.9 JP2.7 JP2.5 JP2.3 JP2.1 JP9.1 | JP2.23 JP2.25 JP2.27 JP2.29 JP2.31 JP2.33 JP2.35 JP2.37 JP2.39 JP2.41 JP2.43 JP2.45 JP2.47 JP2.23
(copper drawn outside any net)
  shapes: Top circle x1

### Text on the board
Top: HEXA-BRAIN V1.0 | - | + | S | DA | . | CL | . | . | . | GND | . | . | . | . | UART2 | 1 | RX | TX | TXD | RXD | GND | K | F | TXD | GND | VCC | 7 | 6 | 5 | 4 | 3 | 2 | 1 | 0 | RXD | GND | ANT | UART1 | ISP | . | POWER | RESET | 1 GND | 2 VCC | 3 GND | ANT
